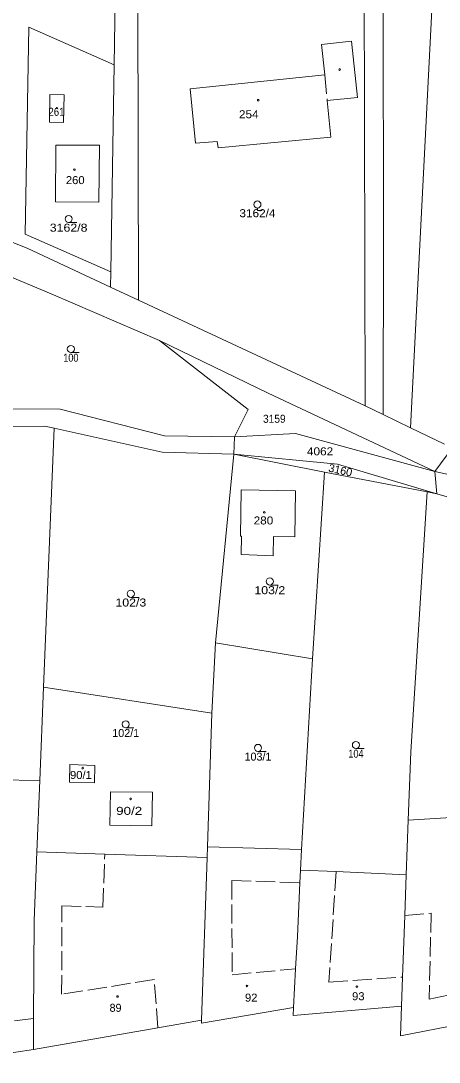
# Model space of a CAD drawing. Extents: x -590528 to -586543, y -1119609 to -1116685.
# Drawn here: x -588794.5 to -588705.8, y -1118502.5 to -1118281.3 of the extents above; entities that cross this region are included whole.
import ezdxf
from ezdxf.enums import TextEntityAlignment as Align

# ---------------------------------------------------------------- set-up
doc = ezdxf.new("R2010")
doc.units = 0
doc.header["$LTSCALE"] = 0.68
doc.linetypes.add('LONG_DASHED', pattern=[7.5, 6, -1.5])
for name, color, linetype, lineweight in [('1', 7, 'Continuous', 13), ('2', 7, 'LONG_DASHED', 13), ('3', 7, 'Continuous', 13), ('6', 7, 'Continuous', 13)]:
    doc.layers.add(name, color=color, linetype=linetype, lineweight=lineweight)

msp = doc.modelspace()

# ---------------------------------------------------------------- linework, layer by layer
at = {"layer": '1'}
for p, q in [((-588717.61, -1118328.06), (-588717.73, -1118271.19)), ((-588769.59, -1118340.66), (-588769.73, -1118272.69)), ((-588724.38, -1118285.69), (-588730.75, -1118286.35)), ((-588730.75, -1118286.35), (-588730.08, -1118292.82)), ((-588723.15, -1118297.63), (-588724.38, -1118285.69)), ((-588730.08, -1118292.82), (-588758.64, -1118295.78)), ((-588729.56, -1118298.3), (-588723.15, -1118297.63)), ((-588729.56, -1118298.3), (-588728.82, -1118306.05)), ((-588787.08, -1118307.77), (-588787.18, -1118319.77)), ((-588787.08, -1118307.77), (-588777.86, -1118307.76)), ((-588777.98, -1118319.86), (-588777.86, -1118307.76)), ((-588787.18, -1118319.77), (-588777.98, -1118319.86)), ((-588793.07, -1118329.73), (-588802.56, -1118325.8)), ((-588717.71, -1118364.94), (-588717.61, -1118328.06)), ((-588775.49, -1118337.9), (-588793.07, -1118329.73)), ((-588775.49, -1118337.9), (-588769.59, -1118340.66)), ((-588769.59, -1118340.66), (-588721.54, -1118363.15)), ((-588765.12, -1118349.22), (-588746.35, -1118363.9)), ((-588742.05, -1118360.45), (-588765.12, -1118349.22)), ((-588721.54, -1118363.15), (-588717.71, -1118364.94)), ((-588711.91, -1118367.77), (-588717.71, -1118364.94)), ((-588787.43, -1118367.9), (-588789.69, -1118422.85)), ((-588749.23, -1118369.68), (-588736.31, -1118369.02)), ((-588736.31, -1118369.02), (-588706.76, -1118377.06)), ((-588711.91, -1118367.77), (-588704.69, -1118371.28)), ((-588749.23, -1118369.68), (-588749.36, -1118373.41)), ((-588764.59, -1118372.94), (-588749.36, -1118373.41)), ((-588730.11, -1118377.23), (-588708.35, -1118381.42)), ((-588706.76, -1118377.06), (-588665, -1118386.32)), ((-588706.76, -1118377.06), (-588706.32, -1118381.81)), ((-588747.95, -1118390.79), (-588747.81, -1118380.99)), ((-588747.81, -1118380.99), (-588736.31, -1118381.15)), ((-588736.45, -1118390.95), (-588736.31, -1118381.15)), ((-588711.83, -1118436.6), (-588708.35, -1118381.42)), ((-588708.35, -1118381.42), (-588706.32, -1118381.81)), ((-588706.32, -1118381.81), (-588688.67, -1118386.99)), ((-588747.75, -1118390.79), (-588747.95, -1118390.79)), ((-588747.8, -1118394.69), (-588747.75, -1118390.79)), ((-588741, -1118394.99), (-588740.95, -1118390.89)), ((-588740.95, -1118390.89), (-588736.45, -1118390.95)), ((-588747.8, -1118394.69), (-588741, -1118394.99)), ((-588754.03, -1118428.43), (-588753.26, -1118413.45)), ((-588734.99, -1118457.39), (-588732.65, -1118416.87)), ((-588789.69, -1118422.85), (-588790.51, -1118442.7)), ((-588789.69, -1118422.85), (-588754.03, -1118428.43)), ((-588784.14, -1118439.28), (-588784.22, -1118443.08)), ((-588784.14, -1118439.28), (-588778.85, -1118439.49)), ((-588778.85, -1118439.49), (-588778.92, -1118443.19)), ((-588806.87, -1118442.44), (-588790.51, -1118442.7)), ((-588784.22, -1118443.08), (-588778.92, -1118443.19)), ((-588775.62, -1118452.18), (-588775.52, -1118445.08)), ((-588775.52, -1118445.08), (-588766.62, -1118445.21)), ((-588766.72, -1118452.31), (-588766.62, -1118445.21)), ((-588712.36, -1118451.15), (-588691.84, -1118449.83)), ((-588775.62, -1118452.18), (-588766.72, -1118452.31)), ((-588791.13, -1118457.82), (-588791.43, -1118465.14)), ((-588754.97, -1118456.81), (-588734.99, -1118457.39)), ((-588735.24, -1118461.72), (-588734.99, -1118457.39)), ((-588755.04, -1118459.08), (-588756.18, -1118493.58)), ((-588735.24, -1118461.72), (-588727.63, -1118462.06)), ((-588713.1, -1118471.38), (-588712.78, -1118462.72)), ((-588791.43, -1118465.14), (-588791.73, -1118472.41)), ((-588713.58, -1118484.45), (-588713.1, -1118471.38)), ((-588736.26, -1118482.7), (-588735.87, -1118475.81)), ((-588756.2, -1118494.23), (-588736.72, -1118490.91)), ((-588736.81, -1118492.6), (-588713.8, -1118490.64)), ((-588714.03, -1118496.94), (-588693.02, -1118492.81)), ((-588791.84, -1118499.82), (-588765.47, -1118495.21)), ((-588765.47, -1118495.21), (-588756.18, -1118493.58)), ((-588756.18, -1118493.58), (-588756.2, -1118494.23)), ((-588791.84, -1118499.82), (-588809.13, -1118502.53))]:
    msp.add_line(p, q, dxfattribs=at)
for points in [[(-588774.74, -1118290.68), (-588774.01, -1118244.1), (-588773.87, -1118234.93)], [(-588717.73, -1118235.71), (-588705.15, -1118235.97), (-588711.91, -1118367.77)], [(-588769.73, -1118272.69), (-588721.73, -1118272.59), (-588721.54, -1118363.15)], [(-588793.58, -1118326.64), (-588792.81, -1118282.72), (-588774.74, -1118290.68)], [(-588775.44, -1118334.67), (-588775.02, -1118307.99), (-588774.74, -1118290.68)], [(-588758.64, -1118295.78), (-588757.49, -1118307.34), (-588752.87, -1118306.98), (-588752.69, -1118308.34), (-588728.82, -1118306.05)], [(-588775.49, -1118337.9), (-588775.44, -1118334.67), (-588793.58, -1118326.64)], [(-588806.53, -1118331.63), (-588788.11, -1118339.36), (-588765.12, -1118349.22)], [(-588742.05, -1118360.45), (-588706.76, -1118377.06), (-588702.93, -1118371.91)], [(-588764.09, -1118369.51), (-588786.16, -1118363.82), (-588803.9, -1118363.73), (-588806.8, -1118363.98), (-588826.14, -1118365.68)], [(-588746.35, -1118363.9), (-588749.23, -1118369.68), (-588764.09, -1118369.51)], [(-588824.56, -1118370.14), (-588806.61, -1118367.61), (-588789.42, -1118367.44), (-588787.43, -1118367.9), (-588764.59, -1118372.94)], [(-588749.36, -1118373.41), (-588727.38, -1118375.48), (-588706.32, -1118381.81)], [(-588755.04, -1118459.08), (-588754.97, -1118456.81), (-588754.03, -1118428.43)], [(-588727.63, -1118462.06), (-588712.78, -1118462.72), (-588712.36, -1118451.15), (-588711.83, -1118436.6)], [(-588790.51, -1118442.7), (-588791.13, -1118457.82), (-588776.74, -1118458.32), (-588755.04, -1118459.08)], [(-588735.87, -1118475.81), (-588735.36, -1118464.42), (-588735.24, -1118461.72)], [(-588791.73, -1118472.41), (-588791.81, -1118493.26), (-588791.84, -1118499.82)], [(-588736.26, -1118482.7), (-588736.72, -1118490.91), (-588736.81, -1118492.6)], [(-588714.03, -1118496.94), (-588713.8, -1118490.64), (-588713.58, -1118484.45)]]:
    msp.add_lwpolyline(points, dxfattribs=at)
for points in [[(-588788.36, -1118297), (-588785.36, -1118297.05), (-588785.46, -1118302.95), (-588788.46, -1118302.9)], [(-588749.36, -1118373.41), (-588730.11, -1118377.23), (-588732.65, -1118416.87), (-588753.26, -1118413.45)]]:
    msp.add_lwpolyline(points, close=True, dxfattribs=at)
at = {"layer": '2'}
for p, q in [((-588730.08, -1118292.82), (-588729.56, -1118298.3)), ((-588777.13, -1118469.62), (-588776.74, -1118458.32)), ((-588727.63, -1118462.06), (-588729.24, -1118485.55)), ((-588749.78, -1118463.93), (-588735.36, -1118464.42)), ((-588785.87, -1118488.12), (-588785.83, -1118469.31)), ((-588785.83, -1118469.31), (-588777.13, -1118469.62)), ((-588713.1, -1118471.38), (-588707.5, -1118470.91)), ((-588707.5, -1118470.91), (-588707.93, -1118489.12)), ((-588729.24, -1118485.55), (-588713.58, -1118484.45)), ((-588766.25, -1118484.97), (-588785.87, -1118488.12)), ((-588765.47, -1118495.21), (-588766.25, -1118484.97)), ((-588791.81, -1118493.26), (-588802.89, -1118494.63))]:
    msp.add_line(p, q, dxfattribs=at)
for points in [[(-588749.78, -1118463.93), (-588749.72, -1118483.97), (-588736.26, -1118482.7)], [(-588707.93, -1118489.12), (-588698.8, -1118487.2), (-588699.08, -1118465.91)]]:
    msp.add_lwpolyline(points, dxfattribs=at)
at = {"layer": '6'}
for p, q in [((-588784.39, -1118324.18), (-588782.64, -1118324.18)), ((-588783.92, -1118351.8), (-588782.17, -1118351.8)), ((-588741.73, -1118401.18), (-588739.98, -1118401.18)), ((-588771.2, -1118403.8), (-588769.45, -1118403.8)), ((-588772.28, -1118431.52), (-588770.53, -1118431.52)), ((-588744.24, -1118436.53), (-588742.49, -1118436.53)), ((-588723.47, -1118435.91), (-588721.72, -1118435.91))]:
    msp.add_line(p, q, dxfattribs=at)
msp.add_lwpolyline([(-588744.35, -1118321.11), (-588744.35, -1118321.61), (-588743.35, -1118321.61)], dxfattribs=at)
for centre, radius in [((-588726.9302, -1118291.6904), 0.175), ((-588744.1902, -1118298.2004), 0.175), ((-588786.8701, -1118299.8702), 0.1172), ((-588783.1602, -1118312.9504), 0.175), ((-588744.35, -1118320.36), 0.75), ((-588784.39, -1118323.43), 0.75), ((-588783.92, -1118351.05), 0.75), ((-588742.9202, -1118385.7504), 0.175), ((-588741.73, -1118400.43), 0.75), ((-588771.2, -1118403.05), 0.75), ((-588772.28, -1118430.77), 0.75), ((-588744.24, -1118435.78), 0.75), ((-588723.47, -1118435.16), 0.75), ((-588781.4002, -1118440.0704), 0.175), ((-588771.2502, -1118446.6104), 0.175), ((-588746.5702, -1118486.3504), 0.175), ((-588723.2602, -1118486.4804), 0.175), ((-588774.0102, -1118488.5804), 0.175)]:
    msp.add_circle(centre, radius, dxfattribs=at)

# ---------------------------------------------------------------- texts
at = {"layer": '3'}
for s, width, p in [('261', 0.9, (-588786.9705, -1118301.52)), ('254', 1.1, (-588746.1805, -1118302.04)), ('260', 1.05, (-588782.9905, -1118316.03)), ('3162/4', 1.1, (-588744.35, -1118323.06)), ('3162/8', 1.15, (-588784.39, -1118326.13)), ('100', 0.85, (-588783.9205, -1118353.75)), ('3159', 0.95, (-588740.77, -1118366.72)), ('4062', 1.1, (-588731.0705, -1118373.64)), ('280', 1.1, (-588743.08, -1118388.32)), ('103/2', 1.15, (-588741.7305, -1118403.13)), ('102/3', 1.15, (-588771.2005, -1118405.75)), ('104', 0.85, (-588723.4705, -1118437.86)), ('90/1', 1.05, (-588781.7805, -1118442.38)), ('90/2', 1.25, (-588771.55, -1118450)), ('92', 1.05, (-588745.671, -1118489.67)), ('93', 1.05, (-588722.9605, -1118489.37))]:
    msp.add_text(s, height=1.7, dxfattribs=dict(at, width=width)).set_placement(p, align=Align.CENTER)
msp.add_text('3160', height=1.7, rotation=347.499, dxfattribs=at).set_placement((-588726.935, -1118377.6203), align=Align.CENTER)
for s, p in [('102/1', (-588772.281, -1118433.47)), ('103/1', (-588744.2405, -1118438.48)), ('89', (-588774.4405, -1118491.83))]:
    msp.add_text(s, height=1.7, dxfattribs=at).set_placement(p, align=Align.CENTER)

doc.saveas('drawing.dxf')
